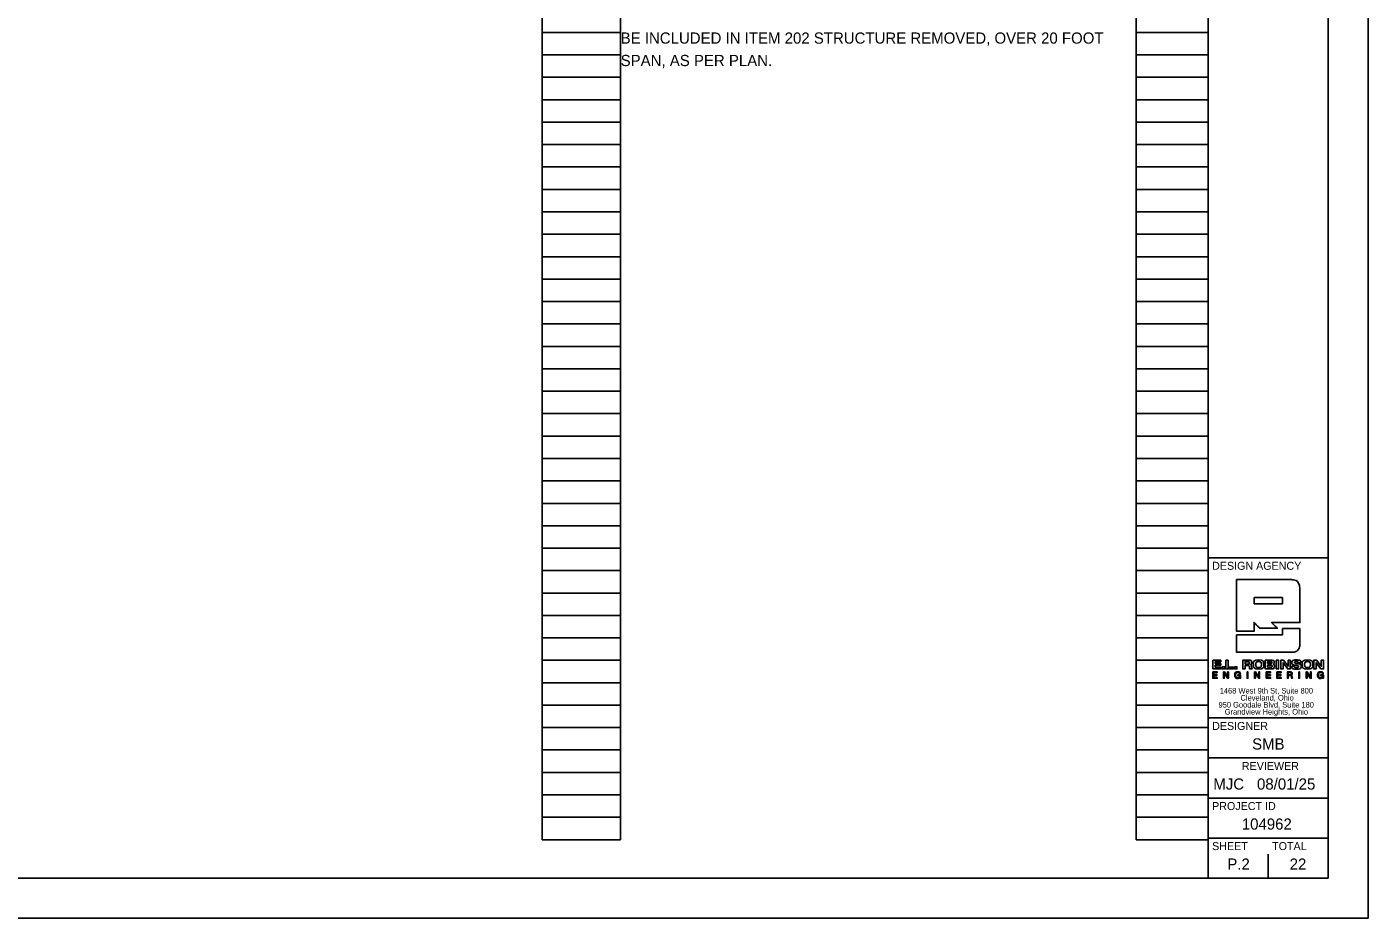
# Model space of a CAD drawing. Extents: x 0 to 34, y 0 to 22.
# Drawn here: x 17.24 to 34, y 0 to 11.13 of the extents above; entities that cross this region are included whole.
import ezdxf

# ---------------------------------------------------------------- set-up
doc = ezdxf.new("R2010")
doc.units = 0
for name, color, linetype in [('SH_Border', 7, 'Continuous'), ('SH_Cut_Line', 7, 'Continuous'), ('SH_Data', 7, 'Continuous'), ('SH_Text', 7, 'Continuous')]:
    doc.layers.add(name, color=color, linetype=linetype)

msp = doc.modelspace()

# ---------------------------------------------------------------- linework, layer by layer
at = {"layer": 'SH_Border'}
for p, q in [((32, 0.5), (32, 21.5)), ((32, 4.5), (33.5, 4.5)), ((32, 2.5), (33.5, 2.5)), ((32, 2), (33.5, 2)), ((32, 1.5), (33.5, 1.5)), ((32, 1), (33.5, 1))]:
    msp.add_line(p, q, dxfattribs=at)
msp.add_lwpolyline([(1.5, 21.5), (33.5, 21.5), (33.5, 0.5), (1.5, 0.5)], close=True, dxfattribs=at)
at = {"layer": 'SH_Cut_Line'}
msp.add_lwpolyline([(0, 0), (34, 0), (34, 22), (0, 22)], close=True, dxfattribs=at)
at = {"layer": 'SH_Data'}
for p, q in [((23.68, 0.98), (23.68, 21.14)), ((24.66, 0.98), (24.66, 21.14)), ((31.1, 0.98), (31.1, 21.14)), ((32, 0.98), (32, 21.14)), ((23.68, 11.06), (24.66, 11.06)), ((31.1, 11.06), (32, 11.06)), ((23.68, 10.78), (24.66, 10.78)), ((31.1, 10.78), (32, 10.78)), ((23.68, 10.5), (24.66, 10.5)), ((31.1, 10.5), (32, 10.5)), ((23.68, 10.22), (24.66, 10.22)), ((31.1, 10.22), (32, 10.22)), ((23.68, 9.94), (24.66, 9.94)), ((31.1, 9.94), (32, 9.94)), ((23.68, 9.66), (24.66, 9.66)), ((31.1, 9.66), (32, 9.66)), ((23.68, 9.38), (24.66, 9.38)), ((31.1, 9.38), (32, 9.38)), ((23.68, 9.1), (24.66, 9.1)), ((31.1, 9.1), (32, 9.1)), ((23.68, 8.82), (24.66, 8.82)), ((31.1, 8.82), (32, 8.82)), ((23.68, 8.54), (24.66, 8.54)), ((31.1, 8.54), (32, 8.54)), ((23.68, 8.26), (24.66, 8.26)), ((31.1, 8.26), (32, 8.26)), ((23.68, 7.98), (24.66, 7.98)), ((31.1, 7.98), (32, 7.98)), ((23.68, 7.7), (24.66, 7.7)), ((31.1, 7.7), (32, 7.7)), ((23.68, 7.42), (24.66, 7.42)), ((31.1, 7.42), (32, 7.42)), ((23.68, 7.14), (24.66, 7.14)), ((31.1, 7.14), (32, 7.14)), ((23.68, 6.86), (24.66, 6.86)), ((31.1, 6.86), (32, 6.86)), ((23.68, 6.58), (24.66, 6.58)), ((31.1, 6.58), (32, 6.58)), ((23.68, 6.3), (24.66, 6.3)), ((31.1, 6.3), (32, 6.3)), ((23.68, 6.02), (24.66, 6.02)), ((31.1, 6.02), (32, 6.02)), ((23.68, 5.74), (24.66, 5.74)), ((31.1, 5.74), (32, 5.74)), ((23.68, 5.46), (24.66, 5.46)), ((31.1, 5.46), (32, 5.46)), ((23.68, 5.18), (24.66, 5.18)), ((31.1, 5.18), (32, 5.18)), ((23.68, 4.9), (24.66, 4.9)), ((31.1, 4.9), (32, 4.9)), ((23.68, 4.62), (24.66, 4.62)), ((31.1, 4.62), (32, 4.62)), ((23.68, 4.34), (24.66, 4.34)), ((31.1, 4.34), (32, 4.34)), ((23.68, 4.06), (24.66, 4.06)), ((31.1, 4.06), (32, 4.06)), ((32.929, 4.003), (32.574, 4.003)), ((32.574, 4.003), (32.574, 3.925)), ((32.574, 3.925), (32.929, 3.925)), ((32.929, 3.925), (32.929, 4.003)), ((23.68, 3.78), (24.66, 3.78)), ((31.1, 3.78), (32, 3.78)), ((23.68, 3.5), (24.66, 3.5)), ((31.1, 3.5), (32, 3.5)), ((32.75, 3.5), (32.75, 3.5)), ((23.68, 3.22), (24.66, 3.22)), ((31.1, 3.22), (32, 3.22)), ((32.463, 3.201), (32.463, 3.173)), ((32.743, 3.202), (32.743, 3.178)), ((32.743, 3.159), (32.743, 3.133)), ((33.001, 3.066), (33.001, 3.039)), ((33.001, 3.039), (33.023, 3.039)), ((23.68, 2.94), (24.66, 2.94)), ((31.1, 2.94), (32, 2.94)), ((23.68, 2.66), (24.66, 2.66)), ((31.1, 2.66), (32, 2.66)), ((23.68, 2.38), (24.66, 2.38)), ((31.1, 2.38), (32, 2.38)), ((23.68, 2.1), (24.66, 2.1)), ((31.1, 2.1), (32, 2.1)), ((23.68, 1.82), (24.66, 1.82)), ((31.1, 1.82), (32, 1.82)), ((23.68, 1.54), (24.66, 1.54)), ((31.1, 1.54), (32, 1.54)), ((23.68, 1.26), (24.66, 1.26)), ((31.1, 1.26), (32, 1.26)), ((23.68, 0.98), (24.66, 0.98)), ((31.1, 0.98), (32, 0.98)), ((32.375, 0.675), (32.375, 0.675)), ((32.75, 0.5), (32.75, 0.8))]:
    msp.add_line(p, q, dxfattribs=at)
for points in [[(32.06, 3.221), (32.161, 3.221), (32.161, 3.201), (32.089, 3.201), (32.089, 3.178), (32.158, 3.178), (32.158, 3.158), (32.089, 3.158), (32.089, 3.133), (32.162, 3.133), (32.162, 3.113), (32.06, 3.113), (32.06, 3.221)], [(32.22, 3.221), (32.249, 3.221), (32.249, 3.134), (32.316, 3.134), (32.316, 3.113), (32.22, 3.113), (32.22, 3.221)], [(32.851, 3.221), (32.881, 3.221), (32.881, 3.113), (32.851, 3.113), (32.851, 3.221)], [(32.999, 3.221), (33.027, 3.221), (33.027, 3.113), (32.995, 3.113), (32.936, 3.189), (32.936, 3.189), (32.936, 3.113), (32.907, 3.113), (32.907, 3.221), (32.941, 3.221), (32.999, 3.146), (32.999, 3.146), (32.999, 3.221)], [(33.413, 3.221), (33.442, 3.221), (33.442, 3.113), (33.41, 3.113), (33.35, 3.189), (33.35, 3.189), (33.35, 3.113), (33.321, 3.113), (33.321, 3.221), (33.356, 3.221), (33.413, 3.146), (33.413, 3.146), (33.413, 3.221)], [(32.059, 3.075), (32.114, 3.075), (32.114, 3.066), (32.07, 3.066), (32.07, 3.041), (32.111, 3.041), (32.111, 3.032), (32.07, 3.032), (32.07, 3.005), (32.114, 3.005), (32.114, 2.996), (32.059, 2.996), (32.059, 3.075)], [(32.175, 3.139), (32.205, 3.139), (32.205, 3.113), (32.175, 3.113), (32.175, 3.139)], [(32.191, 3.075), (32.203, 3.075), (32.244, 3.011), (32.244, 3.011), (32.244, 3.075), (32.254, 3.075), (32.254, 2.996), (32.243, 2.996), (32.202, 3.059), (32.201, 3.059), (32.201, 2.996), (32.191, 2.996), (32.191, 3.075)], [(32.331, 3.139), (32.361, 3.139), (32.361, 3.113), (32.331, 3.113), (32.331, 3.139)], [(32.487, 3.075), (32.498, 3.075), (32.498, 2.996), (32.487, 2.996), (32.487, 3.075)], [(32.581, 3.075), (32.592, 3.075), (32.633, 3.011), (32.633, 3.011), (32.633, 3.075), (32.643, 3.075), (32.643, 2.996), (32.632, 2.996), (32.591, 3.059), (32.591, 3.059), (32.591, 2.996), (32.581, 2.996), (32.581, 3.075)], [(32.726, 3.075), (32.781, 3.075), (32.781, 3.066), (32.737, 3.066), (32.737, 3.041), (32.778, 3.041), (32.778, 3.032), (32.737, 3.032), (32.737, 3.005), (32.781, 3.005), (32.781, 2.996), (32.726, 2.996), (32.726, 3.075)], [(32.859, 3.075), (32.913, 3.075), (32.913, 3.066), (32.869, 3.066), (32.869, 3.041), (32.91, 3.041), (32.91, 3.032), (32.869, 3.032), (32.869, 3.005), (32.913, 3.005), (32.913, 2.996), (32.859, 2.996), (32.859, 3.075)], [(33.133, 3.075), (33.143, 3.075), (33.143, 2.996), (33.133, 2.996), (33.133, 3.075)], [(33.226, 3.075), (33.237, 3.075), (33.279, 3.011), (33.279, 3.011), (33.279, 3.075), (33.289, 3.075), (33.289, 2.996), (33.277, 2.996), (33.236, 3.059), (33.236, 3.059), (33.236, 2.996), (33.226, 2.996), (33.226, 3.075)]]:
    msp.add_lwpolyline(points, dxfattribs=at)
for points, degree in [([(32.356, 3.583), (32.356, 3.586), (32.356, 4.224), (32.356, 4.227)], 2), ([(32.356, 4.227), (32.36, 4.227), (33.03, 4.227), (33.034, 4.227), (33.096, 4.227), (33.147, 4.177), (33.147, 4.114)], 3), ([(33.147, 4.114), (33.147, 4.112), (33.147, 3.694), (33.147, 3.692)], 2), ([(32.645, 3.621), (32.645, 3.621), (32.574, 3.691), (32.574, 3.692)], 2), ([(32.574, 3.692), (32.574, 3.691), (32.574, 3.583), (32.574, 3.583)], 2), ([(33.147, 3.692), (33.145, 3.692), (32.795, 3.692), (32.793, 3.692)], 2), ([(32.793, 3.692), (32.793, 3.691), (32.866, 3.621), (32.866, 3.621)], 2), ([(32.929, 3.615), (32.929, 3.615), (33.147, 3.615), (33.147, 3.615), (33.147, 3.615), (33.147, 3.433), (33.147, 3.433), (33.147, 3.37), (33.096, 3.32), (33.034, 3.32), (33.034, 3.32), (32.356, 3.32), (32.356, 3.32), (32.356, 3.32), (32.356, 3.537), (32.356, 3.537), (32.356, 3.537), (32.929, 3.537), (32.929, 3.537), (32.929, 3.537), (32.929, 3.615), (32.929, 3.615)], 3), ([(32.574, 3.583), (32.573, 3.583), (32.357, 3.583), (32.356, 3.583)], 2), ([(32.866, 3.621), (32.865, 3.621), (32.646, 3.621), (32.645, 3.621)], 2), ([(32.433, 3.113), (32.433, 3.113), (32.433, 3.221), (32.433, 3.221)], 2), ([(32.433, 3.221), (32.433, 3.221), (32.512, 3.221), (32.512, 3.221), (32.542, 3.221), (32.545, 3.203), (32.546, 3.192)], 3), ([(32.463, 3.173), (32.463, 3.173), (32.502, 3.173), (32.502, 3.173), (32.508, 3.173), (32.516, 3.177), (32.516, 3.187), (32.516, 3.198), (32.507, 3.201), (32.5, 3.201), (32.5, 3.201), (32.463, 3.201), (32.463, 3.201), (32.463, 3.201), (32.463, 3.173), (32.463, 3.173)], 3), ([(32.463, 3.173), (32.476, 3.173), (32.489, 3.173), (32.508, 3.173), (32.516, 3.177), (32.516, 3.198), (32.507, 3.201), (32.488, 3.201), (32.475, 3.201), (32.463, 3.201)], 3), ([(32.546, 3.192), (32.544, 3.179), (32.542, 3.17), (32.53, 3.166)], 2), ([(32.631, 3.11), (32.573, 3.11), (32.567, 3.145), (32.565, 3.167), (32.564, 3.19), (32.573, 3.224), (32.631, 3.224)], 3), ([(32.631, 3.13), (32.658, 3.13), (32.667, 3.15), (32.667, 3.167), (32.667, 3.184), (32.658, 3.204), (32.631, 3.204), (32.604, 3.204), (32.595, 3.184), (32.595, 3.167), (32.595, 3.15), (32.604, 3.13), (32.631, 3.13)], 3), ([(32.631, 3.204), (32.604, 3.204), (32.595, 3.184), (32.595, 3.167), (32.595, 3.15), (32.604, 3.13), (32.631, 3.13)], 3), ([(32.631, 3.224), (32.69, 3.224), (32.695, 3.189), (32.697, 3.167), (32.699, 3.144), (32.69, 3.11), (32.631, 3.11)], 3), ([(32.631, 3.13), (32.658, 3.13), (32.667, 3.15), (32.667, 3.167), (32.667, 3.184), (32.658, 3.204), (32.631, 3.204)], 3), ([(32.714, 3.113), (32.714, 3.113), (32.714, 3.221), (32.714, 3.221)], 2), ([(32.714, 3.221), (32.714, 3.221), (32.795, 3.221), (32.795, 3.221)], 2), ([(32.743, 3.178), (32.743, 3.178), (32.784, 3.178), (32.784, 3.178), (32.791, 3.178), (32.796, 3.182), (32.796, 3.19), (32.796, 3.197), (32.793, 3.202), (32.78, 3.202), (32.78, 3.202), (32.743, 3.202), (32.743, 3.202), (32.743, 3.202), (32.743, 3.178), (32.743, 3.178)], 3), ([(32.743, 3.178), (32.757, 3.178), (32.771, 3.178), (32.791, 3.181), (32.791, 3.183), (32.792, 3.197), (32.793, 3.202), (32.768, 3.202), (32.756, 3.202), (32.743, 3.202)], 3), ([(32.795, 3.221), (32.81, 3.218), (32.826, 3.214), (32.826, 3.194)], 2), ([(32.826, 3.194), (32.824, 3.186), (32.822, 3.175), (32.812, 3.172)], 2), ([(33.126, 3.19), (33.124, 3.204), (33.111, 3.206), (33.099, 3.206), (33.087, 3.206), (33.079, 3.2), (33.079, 3.193), (33.079, 3.187), (33.084, 3.184), (33.091, 3.183), (33.091, 3.183), (33.128, 3.177), (33.128, 3.177), (33.148, 3.173), (33.163, 3.166), (33.163, 3.146), (33.163, 3.126), (33.149, 3.11), (33.107, 3.11), (33.08, 3.11), (33.046, 3.113), (33.045, 3.147), (33.045, 3.147), (33.079, 3.147), (33.079, 3.147), (33.079, 3.132), (33.094, 3.129), (33.107, 3.129), (33.121, 3.129), (33.13, 3.134), (33.13, 3.143), (33.13, 3.151), (33.123, 3.154), (33.112, 3.155), (33.112, 3.155), (33.085, 3.16), (33.085, 3.16), (33.066, 3.162), (33.047, 3.168), (33.047, 3.19), (33.047, 3.215), (33.067, 3.224), (33.101, 3.224), (33.124, 3.224), (33.157, 3.221), (33.159, 3.19), (33.159, 3.19), (33.126, 3.19), (33.126, 3.19)], 3), ([(33.242, 3.11), (33.183, 3.11), (33.178, 3.145), (33.176, 3.167), (33.174, 3.19), (33.183, 3.224), (33.242, 3.224)], 3), ([(33.242, 3.13), (33.269, 3.13), (33.278, 3.15), (33.278, 3.167), (33.278, 3.184), (33.269, 3.204), (33.242, 3.204), (33.215, 3.204), (33.205, 3.184), (33.205, 3.167), (33.205, 3.15), (33.215, 3.13), (33.242, 3.13)], 3), ([(33.242, 3.204), (33.215, 3.204), (33.205, 3.184), (33.205, 3.167), (33.205, 3.15), (33.215, 3.13), (33.242, 3.13)], 3), ([(33.242, 3.224), (33.3, 3.224), (33.306, 3.189), (33.308, 3.167), (33.309, 3.144), (33.3, 3.11), (33.242, 3.11)], 3), ([(33.242, 3.13), (33.269, 3.13), (33.278, 3.15), (33.278, 3.167), (33.278, 3.184), (33.269, 3.204), (33.242, 3.204)], 3), ([(32.396, 3.006), (32.39, 2.998), (32.38, 2.994), (32.37, 2.994), (32.347, 2.994), (32.333, 3.014), (32.333, 3.034), (32.333, 3.057), (32.346, 3.077), (32.37, 3.077), (32.388, 3.077), (32.401, 3.069), (32.404, 3.051), (32.404, 3.051), (32.394, 3.051), (32.394, 3.051), (32.392, 3.062), (32.382, 3.068), (32.37, 3.068), (32.351, 3.068), (32.344, 3.051), (32.344, 3.034), (32.344, 3.018), (32.353, 3.003), (32.37, 3.003), (32.387, 3.003), (32.396, 3.015), (32.396, 3.029), (32.396, 3.029), (32.371, 3.029), (32.371, 3.029), (32.371, 3.029), (32.371, 3.038), (32.371, 3.038), (32.371, 3.038), (32.405, 3.038), (32.405, 3.038), (32.405, 3.038), (32.405, 2.996), (32.405, 2.996), (32.405, 2.996), (32.398, 2.996), (32.398, 2.996), (32.398, 2.996), (32.396, 3.006), (32.396, 3.006)], 3), ([(32.463, 3.113), (32.462, 3.113), (32.433, 3.113), (32.433, 3.113)], 2), ([(32.499, 3.153), (32.499, 3.153), (32.463, 3.153), (32.463, 3.153)], 2), ([(32.463, 3.153), (32.463, 3.152), (32.463, 3.113), (32.463, 3.113)], 2), ([(32.518, 3.113), (32.516, 3.118), (32.516, 3.122), (32.516, 3.134), (32.515, 3.149), (32.508, 3.15), (32.499, 3.153)], 3), ([(32.55, 3.113), (32.55, 3.113), (32.518, 3.113), (32.518, 3.113)], 2), ([(32.53, 3.166), (32.53, 3.166), (32.53, 3.165), (32.53, 3.165)], 2), ([(32.53, 3.165), (32.543, 3.163), (32.544, 3.147), (32.544, 3.136)], 2), ([(32.544, 3.136), (32.544, 3.131), (32.548, 3.119), (32.55, 3.113)], 2), ([(32.829, 3.145), (32.827, 3.132), (32.824, 3.113), (32.791, 3.113), (32.791, 3.113), (32.714, 3.113), (32.714, 3.113)], 3), ([(32.743, 3.133), (32.743, 3.133), (32.787, 3.133), (32.787, 3.133), (32.796, 3.133), (32.8, 3.139), (32.8, 3.146), (32.8, 3.155), (32.794, 3.159), (32.784, 3.159), (32.784, 3.159), (32.743, 3.159), (32.743, 3.159), (32.743, 3.159), (32.743, 3.133), (32.743, 3.133)], 3), ([(32.743, 3.133), (32.758, 3.133), (32.772, 3.133), (32.796, 3.133), (32.8, 3.139), (32.8, 3.155), (32.794, 3.159), (32.77, 3.159), (32.757, 3.159), (32.743, 3.159)], 3), ([(32.812, 3.172), (32.812, 3.172), (32.812, 3.172), (32.812, 3.172)], 2), ([(32.812, 3.172), (32.824, 3.17), (32.827, 3.156), (32.829, 3.145)], 2), ([(32.991, 3.075), (32.991, 3.075), (33.027, 3.075), (33.028, 3.075), (33.042, 3.075), (33.051, 3.067), (33.051, 3.054)], 3), ([(32.991, 2.996), (32.991, 2.997), (32.991, 3.074), (32.991, 3.075)], 2), ([(33.023, 3.039), (33.033, 3.039), (33.041, 3.041), (33.041, 3.052), (33.041, 3.06), (33.037, 3.066), (33.027, 3.066), (33.027, 3.066), (33.001, 3.066), (33.001, 3.066), (33.001, 3.066), (33.001, 3.039), (33.001, 3.039), (33.001, 3.039), (33.023, 3.039), (33.023, 3.039)], 3), ([(33.023, 3.039), (33.033, 3.039), (33.041, 3.041), (33.041, 3.06), (33.037, 3.066), (33.018, 3.066), (33.01, 3.066), (33.001, 3.066)], 3), ([(33.04, 3.016), (33.038, 3.023), (33.037, 3.03), (33.027, 3.03), (33.027, 3.03), (33.001, 3.03), (33.001, 3.03)], 3), ([(33.001, 3.03), (33.001, 3.03), (33.001, 2.996), (33.001, 2.996)], 2), ([(33.051, 3.054), (33.049, 3.045), (33.047, 3.037), (33.038, 3.034)], 2), ([(33.038, 3.034), (33.038, 3.034), (33.038, 3.034), (33.038, 3.034)], 2), ([(33.038, 3.034), (33.044, 3.029), (33.047, 3.025), (33.048, 3.018)], 2), ([(33.048, 3.018), (33.049, 3.01), (33.052, 3.002), (33.054, 2.996)], 2), ([(33.43, 3.006), (33.424, 2.998), (33.414, 2.994), (33.405, 2.994), (33.382, 2.994), (33.368, 3.014), (33.368, 3.034), (33.368, 3.057), (33.38, 3.077), (33.405, 3.077), (33.422, 3.077), (33.436, 3.069), (33.439, 3.051), (33.439, 3.051), (33.429, 3.051), (33.429, 3.051), (33.426, 3.062), (33.417, 3.068), (33.405, 3.068), (33.386, 3.068), (33.378, 3.051), (33.378, 3.034), (33.378, 3.018), (33.388, 3.003), (33.405, 3.003), (33.421, 3.003), (33.431, 3.015), (33.43, 3.029), (33.43, 3.029), (33.405, 3.029), (33.405, 3.029), (33.405, 3.029), (33.405, 3.038), (33.405, 3.038), (33.405, 3.038), (33.44, 3.038), (33.44, 3.038), (33.44, 3.038), (33.44, 2.996), (33.44, 2.996), (33.44, 2.996), (33.433, 2.996), (33.433, 2.996), (33.433, 2.996), (33.43, 3.006), (33.43, 3.006)], 3), ([(33.001, 2.996), (33.001, 2.996), (32.991, 2.996), (32.991, 2.996)], 2), ([(33.043, 2.996), (33.042, 3), (33.041, 3.008), (33.04, 3.016)], 2), ([(33.054, 2.996), (33.054, 2.996), (33.043, 2.996), (33.043, 2.996)], 2)]:
    msp.add_open_spline(points, degree=degree, dxfattribs=at)

# ---------------------------------------------------------------- texts
for s, height, p in [('DESIGN AGENCY', 0.1, (32.05, 4.35)), ('1468 West 9th St, Suite 800', 0.07, (32.145, 2.805)), ('950 Goodale Blvd, Suite 180', 0.07, (32.13, 2.63)), ('Cleveland, Ohio', 0.07, (32.404, 2.717)), ('Grandview Heights, Ohio', 0.07, (32.208, 2.542)), ('DESIGNER', 0.1, (32.05, 2.35)), ('SMB', 0.14, (32.55, 2.105)), ('REVIEWER', 0.1, (32.422, 1.85)), ('MJC', 0.14, (32.065, 1.605)), ('08/01/25', 0.14, (32.611, 1.605)), ('PROJECT ID', 0.1, (32.05, 1.35)), ('104962', 0.14, (32.421, 1.105)), ('SHEET', 0.1, (32.05, 0.85)), ('TOTAL', 0.1, (32.8, 0.85)), ('P.2', 0.14, (32.24, 0.605)), ('22', 0.14, (33.019, 0.605))]:
    msp.add_text(s, height=height, dxfattribs=at).set_placement(p)
at = {"layer": 'SH_Text'}
for s, p in [('BE INCLUDED IN ITEM 202 STRUCTURE REMOVED, OVER 20 FOOT ', (24.66, 10.92)), ('SPAN, AS PER PLAN.', (24.66, 10.64))]:
    msp.add_text(s, height=0.14, dxfattribs=at).set_placement(p)

doc.saveas('drawing.dxf')
